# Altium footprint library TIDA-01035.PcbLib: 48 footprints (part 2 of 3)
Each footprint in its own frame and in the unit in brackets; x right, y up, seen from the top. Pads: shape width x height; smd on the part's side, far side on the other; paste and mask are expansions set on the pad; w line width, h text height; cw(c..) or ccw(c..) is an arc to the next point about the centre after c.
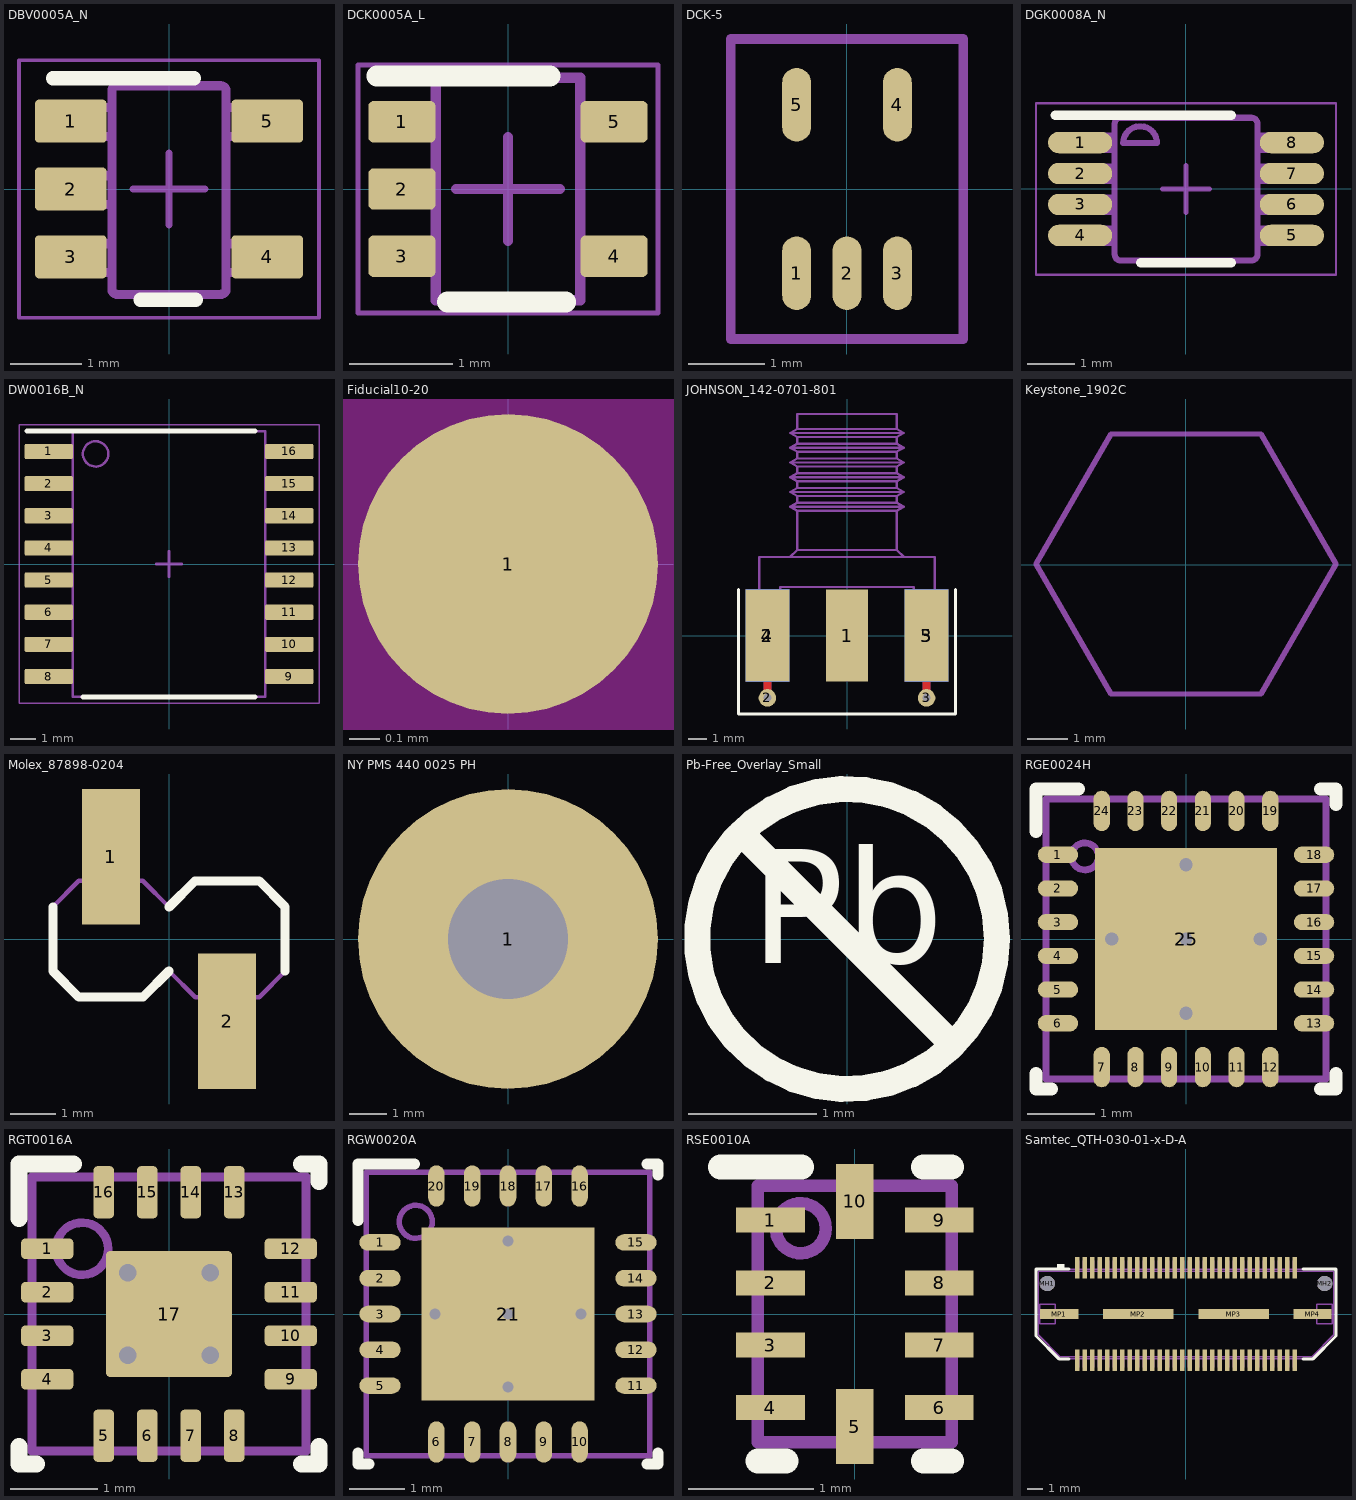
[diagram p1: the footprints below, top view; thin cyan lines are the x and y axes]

## DBV0005A_N [mm] "SOT23, 5-Leads, Body 2.9x1.6mm, Pitch 0.95mm, Lead Span 2.8mm, IPC Medium Density"
height 1.45
pads (5):
  rrect17% 1x0.6 smd: 1(-1.375,0.95) 2(-1.375,0) 3(-1.375,-0.95) 4(1.375,-0.95) 5(1.375,0.95)
Top Overlay:
  lines w0.2: -1.625,1.55 0.35,1.55 ; -0.4,-1.55 0.375,-1.55
Mechanical 5:
  lines w0.127: -0.801,1.371 cw(c-0.725,1.37) -0.725,1.446 ; -0.801,1.37 -0.801,-1.399 -0.801,-1.4 ccw(c-0.725,-1.399) -0.725,-1.475 ; -0.801,1.37 -0.801,1.371 ; -0.725,-1.475 -0.725,-1.475 ; -0.725,-1.475 0.723,-1.475 0.724,-1.475 ccw(c0.723,-1.399) 0.799,-1.4 0.799,-1.399 0.799,1.37 ; -0.725,1.446 0.723,1.446 0.724,1.446 cw(c0.723,1.37) 0.799,1.371 ; -0.725,1.446 -0.725,1.446 ; 0.799,1.37 0.799,1.371 ; -1.423,-1.167 -1.199,-1.167 -1.105,-1.167 -1.088,-1.167 -0.835,-1.167 -0.801,-1.167 -0.801,-0.767 -0.835,-0.767 -1.088,-0.767 -1.105,-0.767 -1.199,-0.767 -1.423,-0.767 -1.423,-1.167 ; -1.423,-0.215 -1.199,-0.215 -1.105,-0.215 -1.088,-0.215 -0.835,-0.215 -0.801,-0.215 -0.801,0.186 -0.835,0.186 -1.088,0.186 -1.105,0.186 -1.199,0.186 -1.423,0.186 -1.423,-0.215 ; -1.423,0.738 -1.199,0.738 -1.105,0.738 -1.088,0.738 -0.835,0.738 -0.801,0.738 -0.801,1.138 -0.835,1.138 -1.088,1.138 -1.105,1.138 -1.199,1.138 -1.423,1.138 -1.423,0.738 ; 0.799,-1.167 0.799,-0.767 0.834,-0.767 1.087,-0.767 1.103,-0.767 1.198,-0.767 1.422,-0.767 1.422,-1.167 1.198,-1.167 1.103,-1.167 1.087,-1.167 0.834,-1.167 0.799,-1.167 ; 0.799,0.738 0.799,1.138 0.834,1.138 1.087,1.138 1.103,1.138 1.198,1.138 1.422,1.138 1.422,0.738 1.198,0.738 1.103,0.738 1.087,0.738 0.834,0.738 0.799,0.738
  text ".Designator" at -0.25,0.95 h0.51
Mechanical 15:
  lines w0.05: -2.1,-1.8 2.1,-1.8 2.1,1.8 -2.1,1.8 -2.1,-1.8
  lines w0.1: -0.5,0 0.5,0 ; 0,-0.5 0,0.5
3D body: height 1.09, standoff 0, extent -1.422,-1.461 1.423,1.46

## DCK0005A_L [mm] "SOT353, 5-Leads, Body 2x1.3mm, Pitch 0.65mm, Lead Span 2.1mm, IPC High Density"
height 1.1
pads (5):
  rrect25% 0.65x0.4 smd: 1(-1.025,0.65) 2(-1.025,0) 3(-1.025,-0.65) 4(1.025,-0.65) 5(1.025,0.65)
Top Overlay:
  lines w0.2: -1.27,1.092 0.406,1.092 ; -0.584,-1.092 0.559,-1.092
Mechanical 5:
  lines w0.1: -0.7,-1.075 0.7,-1.075 0.7,1.075 -0.7,1.075 -0.7,-1.075
  lines w0.127: -0.865,0.762 -0.853,0.762 ; -0.711,-0.763 -0.853,-0.763 -0.865,-0.763 -0.959,-0.763 -1.143,-0.763 -1.143,-0.538 -0.959,-0.538 -0.865,-0.538 -0.853,-0.538 -0.711,-0.538 ; -0.711,-0.113 -0.853,-0.113 -0.865,-0.113 -0.959,-0.113 -1.143,-0.113 -1.143,0.112 -0.959,0.112 -0.865,0.112 -0.853,0.112 -0.711,0.112 ; -0.711,0.537 -0.853,0.537 -0.865,0.537 -0.959,0.537 -1.143,0.537 -1.143,0.762 -0.959,0.762 -0.711,0.762 ; 0.711,-0.763 0.847,-0.763 0.859,-0.763 0.953,-0.763 1.137,-0.763 1.137,-0.538 0.953,-0.538 0.859,-0.538 0.847,-0.538 0.711,-0.538 ; 0.711,0.537 0.847,0.537 0.859,0.537 0.953,0.537 1.137,0.537 1.137,0.762 0.953,0.762 0.859,0.762 0.847,0.762 0.711,0.762
  text ".Designator" at -0.254,0.914 h0.51
Mechanical 15:
  lines w0.05: -1.45,-1.2 -1.45,1.2 1.45,1.2 1.45,-1.2 -1.45,-1.2
  lines w0.1: -0.5,0 0.5,0 ; 0,-0.5 0,0.5
3D body: height 0.95, standoff 0, extent -1.14,-1 1.14,1

## DCK-5 [mil]
pads (5):
  oval 15x38 smd: 1(-25.9,-43.4) 2(0.1,-43.4) 3(26.1,-43.4) 4(26.1,43.6) 5(-25.9,43.6)
Mechanical 5:
  lines w5: -59.9,-77.4 60.1,-77.4 60.1,77.6 -59.9,77.6 -59.9,-77.4
  text "*" at -40,-55 h25
  text ".Designator" at -50,-15 h28

## DGK0008A_N [mm] "TSOP, 8-Leads, Body 3x3mm, Pitch 0.65mm, IPC Medium Density"
height 1.1
pads (8):
  oval 1.35x0.45 smd: 1(-2.225,0.975) 2(-2.225,0.325) 3(-2.225,-0.325) 4(-2.225,-0.975) 5(2.225,-0.975) 6(2.225,-0.325) 7(2.225,0.325) 8(2.225,0.975)
Top Overlay:
  lines w0.2: -2.75,1.55 0.95,1.55 ; -0.95,-1.55 0.95,-1.55
Mechanical 5:
  lines w0.127: -2.45,-1.131 -2.45,-0.826 -2.21,-0.826 -2.091,-0.826 -2.087,-0.826 -1.784,-0.826 -1.498,-0.826 -1.498,-1.131 -1.784,-1.131 -2.087,-1.131 -2.091,-1.131 -2.21,-1.131 -2.45,-1.131 ; -2.45,-0.48 -2.45,-0.175 -2.21,-0.175 -2.091,-0.175 -2.087,-0.175 -1.784,-0.175 -1.498,-0.175 -1.498,-0.48 -1.784,-0.48 -2.087,-0.48 -2.091,-0.48 -2.21,-0.48 -2.45,-0.48 ; -2.45,0.17 -2.45,0.475 -2.21,0.475 -2.091,0.475 -2.087,0.475 -1.784,0.475 -1.498,0.475 -1.498,0.17 -1.784,0.17 -2.087,0.17 -2.091,0.17 -2.21,0.17 -2.45,0.17 ; -2.45,0.82 -2.45,1.125 -2.21,1.125 -2.091,1.125 -2.087,1.125 -1.784,1.125 -1.498,1.125 -1.498,0.82 -1.784,0.82 -2.087,0.82 -2.091,0.82 -2.21,0.82 -2.45,0.82 ; -1.497,-1.377 ccw(c-1.37,-1.374) -1.373,-1.501 -1.371,-1.501 1.373,-1.501 1.375,-1.501 ccw(c1.373,-1.374) 1.5,-1.377 1.5,-1.374 1.5,1.369 1.5,1.372 ccw(c1.373,1.369) 1.375,1.496 1.373,1.496 -1.371,1.496 -1.373,1.496 ccw(c-1.37,1.369) -1.497,1.372 -1.498,1.369 -1.498,-1.374 -1.497,-1.377 ; -1.32,0.962 cw(c-0.964,0.962) -0.609,0.962 -1.32,0.962 ; 1.5,-1.131 1.786,-1.131 2.089,-1.131 2.093,-1.131 2.213,-1.131 2.452,-1.131 2.452,-0.826 2.213,-0.826 2.093,-0.826 2.089,-0.826 1.786,-0.826 1.5,-0.826 1.5,-1.131 ; 1.5,-0.48 1.786,-0.48 2.089,-0.48 2.093,-0.48 2.213,-0.48 2.452,-0.48 2.452,-0.175 2.213,-0.175 2.093,-0.175 2.089,-0.175 1.786,-0.175 1.5,-0.175 1.5,-0.48 ; 1.5,0.17 1.786,0.17 2.089,0.17 2.093,0.17 2.213,0.17 2.452,0.17 2.452,0.475 2.213,0.475 2.093,0.475 2.089,0.475 1.786,0.475 1.5,0.475 1.5,0.17 ; 1.5,0.82 1.786,0.82 2.089,0.82 2.093,0.82 2.213,0.82 2.452,0.82 2.452,1.125 2.213,1.125 2.093,1.125 2.089,1.125 1.786,1.125 1.5,1.125 1.5,0.82
  text ".Designator" at -1.15,-0.3 h0.64
Mechanical 15:
  lines w0.05: -3.15,-1.8 -3.15,1.8 3.15,1.8 3.15,-1.8 -3.15,-1.8
  lines w0.1: -0.5,0 0.5,0 ; 0,-0.5 0,0.5
3D body: height 0.96, standoff 0, extent -2.451,-1.499 2.451,1.499

## DW0016B_N [mm] "SOIC, 16-Leads, Body 10.5x7.6mm, Pitch 1.27mm, IPC Medium Density"
height 2.65
pads (16):
  rrect17% 1.9x0.6 smd: 1(-4.75,4.445) 2(-4.75,3.175) 3(-4.75,1.905) 4(-4.75,0.635) 5(-4.75,-0.635) 6(-4.75,-1.905) 7(-4.75,-3.175) 8(-4.75,-4.445) 9(4.75,-4.445) 10(4.75,-3.175) 11(4.75,-1.905) 12(4.75,-0.635) 13(4.75,0.635) 14(4.75,1.905) 15(4.75,3.175) 16(4.75,4.445)
Top Overlay:
  lines w0.2: -5.6,5.25 3.4,5.25 ; -3.4,-5.25 3.4,-5.25
Mechanical 5:
  circle w0.1: c-2.9,4.35 r0.5
  lines w0.1: -3.8,-5.25 -3.8,5.25 3.8,5.25 3.8,-5.25 -3.8,-5.25
  text ".Designator" at -2.179,-0.358 h1.02
Mechanical 15:
  lines w0.05: -5.925,-5.5 -5.925,5.5 5.925,5.5 5.925,-5.5 -5.925,-5.5
  lines w0.1: -0.5,0 0.5,0 ; 0,-0.5 0,0.5
3D body: height 2.59, standoff 0, extent -5.167,-5.15 5.167,5.15

## Fiducial10-20 [mm]
height 0.69
pads (1):
  round 1 smd mask+0.5: 1(0,0)
Top Layer keep-out:
  circle w1.178: c0,0 r0.5

## JOHNSON_142-0701-801 [mil] "Johnson Components recommended land pattern"
height 119
pads (7):
  rect 90x200 smd: 1(0,0)
  round 38 hole 18: 2(-172.5,-135) 3(172.5,-135)
  rect 95x200 smd: 2(-172.5,0) 3(172.5,0)
  rect 95x200 smd far side: 4(-172.5,0) 5(172.5,0)
Top Layer:
  lines w18: -172.5,-135 -172.5,0 ; 172.5,-135 172.5,0
Bottom Layer:
  lines w18: -172.5,-135 -172.5,0 ; 172.5,-135 172.5,0
Top Overlay:
  lines w7: -235,100 -235,-170 0,-170 235,-170 235,100
Mechanical 5:
  lines w5: -123.5,170.38 -108,185.38 ; 123.5,170.38 108,185.38 ; -123,279.27 -108,270.62 ; -123,279.27 -108,287.94 ; -123,279.27 123,279.27 ; -123,311.27 -108,319.94 ; -123,311.27 -108,302.62 ; -123,311.27 123,311.27 ; -123,343.27 -108,351.94 ; -123,343.27 -108,334.62 ; -123,343.27 123,343.27 ; -123,375.27 -108,383.94 ; -123,375.27 -108,366.62 ; -123,375.27 123,375.27 ; -123,407.27 -108,398.62 ; -123,407.27 -108,415.94 ; -123,407.27 123,407.27 ; -123,439.27 -108,430.62 ; -123,439.27 -108,447.94 ; -123,439.27 123,439.27 ; -108,185.38 -108,270.62 ; -108,185.38 108,185.38 ; -108,270.62 108,270.62 ; -108,287.94 -108,302.62 ; -108,287.94 108,287.94 ; -108,302.62 108,302.62 ; -108,319.94 -108,334.62 ; -108,319.94 108,319.94 ; -108,334.62 108,334.62 ; -108,351.94 -108,366.62 ; -108,351.94 108,351.94 ; -108,366.62 108,366.62 ; -108,383.94 -108,398.62 ; -108,383.94 108,383.94 ; -108,398.62 108,398.62 ; -108,415.94 -108,430.62 ; -108,415.94 108,415.94 ; -108,430.62 108,430.62 ; -108,447.94 -108,480.38 108,480.38 108,447.94 ; -108,447.94 108,447.94 ; 108,185.38 108,270.62 ; 108,270.62 123,279.27 ; 108,287.94 123,279.27 ; 108,287.94 108,302.62 ; 108,302.62 123,311.27 ; 108,319.94 108,334.62 ; 108,319.94 123,311.27 ; 108,334.62 123,343.27 ; 108,351.94 108,366.62 ; 108,351.94 123,343.27 ; 108,366.62 123,375.27 ; 108,383.94 108,398.62 ; 108,383.94 123,375.27 ; 108,398.62 123,407.27 ; 108,415.94 123,407.27 ; 108,415.94 108,430.62 ; 108,430.62 123,439.27 ; 108,447.94 123,439.27 ; -190,-91.62 -190,170.38 190,170.38 190,-91.62 145,-91.62 145,105.38 -145,105.38 -145,-91.62 -190,-91.62
  text ".Designator" at -66.5,-31 h60
3D body: height 164.6, standoff -152.4, extent -190,-92 190,480

## Keystone_1902C [mil] "Hex Standoff, 4-40 threaded, nylon"
height 500
pads (1):
  round 1 on Mech3: 0(0,0)
Mechanical 5:
  lines w5: -145.29,0.49 -72.56,126.47 72.92,126.47 145.65,0.49 72.92,-125.49 -72.56,-125.49 -145.29,0.49
  text ".Designator" at -60,-20 h40
3D body: height 501, standoff 1, extent -144.95,-125.98 146,125.98

## Molex_87898-0204 [mm] "Header, 2.54 mm, 2x1, R/A, SMT"
height 9.65
pads (2):
  rect 1.27x2.96 smd: 1(-1.27,1.8) 2(1.27,-1.8)
Top Overlay:
  lines w0.2: -2.54,0.7 -2.54,-0.7 -1.97,-1.27 -0.57,-1.27 0,-0.7 ; 0,0.7 0.57,1.27 1.97,1.27 2.54,0.7 2.54,-0.7
Mechanical 5:
  lines w0.1: -1.615,1.27 -1.615,2.4 -0.925,2.4 -0.925,1.27 ; 0.925,-1.27 0.925,-2.4 1.615,-2.4 1.615,-1.27 ; -2.54,-0.7 -2.54,0.7 -1.97,1.27 -0.57,1.27 0,0.7 0.57,1.27 1.97,1.27 2.54,0.7 2.54,-0.7 1.97,-1.27 0.57,-1.27 0,-0.7 -0.57,-1.27 -1.97,-1.27 -2.54,-0.7
  text ".Designator" at -1.524,-0.508 h1.02
3D body: height 0.69, standoff 0, extent 0.925,-2.4 1.615,0.345
3D body: height 3.81, standoff 1.32, extent 0,-1.27 2.54,1.27
3D body: height 3.81, standoff 1.32, extent -2.54,-1.27 0,1.27
3D body: height 0.69, standoff 0, extent -1.615,-0.345 -0.925,2.4
3D body: height 9.65, standoff 0, extent 0.926,-0.344 1.614,0.344
3D body: height 9.65, standoff 0, extent -1.614,-0.344 -0.926,0.344
3D body: height 3.81, standoff 1.32, extent 0,-0.7 0,-0.7
3D body: height 3.81, standoff 1.32, extent 0,-0.7 0,-0.7

## NY PMS 440 0025 PH [mm] "4-40 nylon screw and mounting hole"
height 1.905
pads (1):
  round 8 hole 3.2: 1(0,0)
Mechanical 5:
  circle w0.127: c0,0 r3.789
  text ".Designator" at -1.524,-0.508 h1.02
3D body: height 2.69, standoff -8.74, extent -3.302,-3.3 3.296,3.3

## Pb-Free_Overlay_Small [mm]
height 0.69
Top Overlay:
  circle w0.203: c0,0 r1.168
  lines w0.203: -0.826,0.826 0.826,-0.826
  text "Pb" at -0.752,-0.48 h1.52

## RGE0024H [mm] "QFN, 24-Leads, Body 4x4mm, Pitch 0.5mm, Thermal Pad 2.7x2.7mm, TI Recommended"
height 1
pads (25):
  oval 0.6x0.24 smd: 1(-1.9,1.25) 2(-1.9,0.75) 3(-1.9,0.25) 4(-1.9,-0.25) 5(-1.9,-0.75) 6(-1.9,-1.25) 13(1.9,-1.25) 14(1.9,-0.75) 15(1.9,-0.25) 16(1.9,0.25) 17(1.9,0.75) 18(1.9,1.25)
  oval 0.24x0.6 smd: 7(-1.25,-1.9) 8(-0.75,-1.9) 9(-0.25,-1.9) 10(0.25,-1.9) 11(0.75,-1.9) 12(1.25,-1.9) 19(1.25,1.9) 20(0.75,1.9) 21(0.25,1.9) 22(-0.25,1.9) 23(-0.75,1.9) 24(-1.25,1.9)
  rect 2.7x2.7 smd paste-1.35: 25(0,0)
via 0,1.1 diameter 0.5 hole 0.2
via -1.1,0 diameter 0.5 hole 0.2
via 0,0 diameter 0.5 hole 0.2
via 1.1,0 diameter 0.5 hole 0.2
via 0,-1.1 diameter 0.5 hole 0.2
Top Overlay:
  lines w0.2: -2.225,-2 -2.225,-2.225 -2,-2.225 ; -2.225,1.6 -2.225,2.225 -1.6,2.225 ; 2,-2.225 2.225,-2.225 2.225,-2 ; 2,2.225 2.225,2.225 2.225,2
Top Paste:
  rectangle: 0.1,0.1 1.288,1.288
  region: -0.1,1.288 -1.288,1.288 -1.288,0.1 -0.1,0.1
  region: -0.1,-0.1 -1.288,-0.1 -1.288,-1.288 -0.1,-1.288
  rectangle: 0.1,-1.288 1.288,-0.1
Mechanical 5:
  circle w0.1: c-1.5,1.225 r0.2
  lines w0.1: -2.075,-2.075 -2.075,2.075 2.075,2.075 2.075,-2.075 -2.075,-2.075
  text ".Designator" at -1.854,-0.508 h1.02
3D body: height 1, standoff 0, extent -2.075,-2.075 2.075,2.075
3D body: height 1.01, standoff 0.5, extent -1.703,1.022 -1.297,1.428

## RGT0016A [mm] "QFN, 16-Leads, Body 3x3mm, Pitch 0.5mm, Thermal Pad 1.45x1.45mm, TI Recommended"
height 1
pads (17):
  rrect42% 0.6x0.24 smd: 1(-1.4,0.75) 2(-1.4,0.25) 3(-1.4,-0.25) 4(-1.4,-0.75) 9(1.4,-0.75) 10(1.4,-0.25) 11(1.4,0.25) 12(1.4,0.75)
  rrect42% 0.24x0.6 smd: 5(-0.75,-1.4) 6(-0.25,-1.4) 7(0.25,-1.4) 8(0.75,-1.4) 13(0.75,1.4) 14(0.25,1.4) 15(-0.25,1.4) 16(-0.75,1.4)
  rrect7% 1.45x1.45 smd paste-0.725: 17(0,0)
via -0.475,0.475 diameter 0.5 hole 0.2
via -0.475,-0.475 diameter 0.5 hole 0.2
via 0.475,-0.475 diameter 0.5 hole 0.2
via 0.475,0.475 diameter 0.5 hole 0.2
Top Overlay:
  lines w0.2: -1.725,-1.525 -1.725,-1.725 -1.525,-1.725 ; -1.725,1.1 -1.725,1.725 -1.1,1.725 ; 1.525,-1.725 1.725,-1.725 1.725,-1.525 ; 1.525,1.725 1.725,1.725 1.725,1.525
Top Paste:
  rectangle: -0.668,-0.669 0.669,0.669
Mechanical 5:
  circle w0.1: c-1,0.75 r0.3
  lines w0.1: -1.575,-1.575 -1.575,1.575 1.575,1.575 1.575,-1.575 -1.575,-1.575
  text ".Designator" at -1.397,-1.016 h0.76
3D body: height 1, standoff 0, extent -1.575,-1.575 1.575,1.575
3D body: height 1.01, standoff 0.5, extent -1.305,0.445 -0.695,1.055

## RGW0020A [mm] "QFN, 20-Leads, Body 5x5mm, Pitch 0.65mm, Thermal Pad 3.15x3.15mm, TI Recommended"
height 1
pads (21):
  oval 0.75x0.3 smd: 1(-2.325,1.3) 2(-2.325,0.65) 3(-2.325,0) 4(-2.325,-0.65) 5(-2.325,-1.3) 11(2.325,-1.3) 12(2.325,-0.65) 13(2.325,0) 14(2.325,0.65) 15(2.325,1.3)
  oval 0.3x0.75 smd: 6(-1.3,-2.325) 7(-0.65,-2.325) 8(0,-2.325) 9(0.65,-2.325) 10(1.3,-2.325) 16(1.3,2.325) 17(0.65,2.325) 18(0,2.325) 19(-0.65,2.325) 20(-1.3,2.325)
  rect 3.15x3.15 smd paste-1.575: 21(0,0)
via 0,1.325 diameter 0.5 hole 0.2
via -1.325,0 diameter 0.5 hole 0.2
via 0,0 diameter 0.5 hole 0.2
via 1.325,0 diameter 0.5 hole 0.2
via 0,-1.325 diameter 0.5 hole 0.2
Top Overlay:
  lines w0.2: -2.725,-2.525 -2.725,-2.725 -2.525,-2.725 ; -2.725,1.7 -2.725,2.725 -1.7,2.725 ; 2.525,-2.725 2.725,-2.725 2.725,-2.525 ; 2.525,2.725 2.725,2.725 2.725,2.525
Top Paste:
  rectangle: 0.1,0.1 1.468,1.468
  region: -0.1,1.468 -1.468,1.468 -1.468,0.1 -0.1,0.1
  region: -0.1,-0.1 -1.468,-0.1 -1.468,-1.468 -0.1,-1.468
  rectangle: 0.1,-1.468 1.468,-0.1
Mechanical 5:
  circle w0.1: c-1.675,1.675 r0.3
  lines w0.1: -2.575,-2.575 -2.575,2.575 2.575,2.575 2.575,-2.575 -2.575,-2.575
  text ".Designator" at -1.854,-0.508 h1.02
3D body: height 1, standoff 0, extent -2.575,-2.575 2.575,2.575
3D body: height 1.01, standoff 0.5, extent -1.98,1.37 -1.37,1.98

## RSE0010A [mm] "QFN, 10-Leads, Body 1.5x2mm, Pitch 0.5mm, TI Recommended"
height 0.6
pads (10):
  rect 0.55x0.2 smd: 1(-0.675,0.75) 2(-0.675,0.25) 3(-0.675,-0.25) 4(-0.675,-0.75) 6(0.675,-0.75) 7(0.675,-0.25) 8(0.675,0.25) 9(0.675,0.75)
  rect 0.3x0.6 smd: 5(0,-0.9) 10(0,0.9)
Top Overlay:
  lines w0.2: -1.075,1.175 -0.425,1.175 ; -0.775,-1.175 -0.55,-1.175 ; 0.55,-1.175 0.775,-1.175 ; 0.55,1.175 0.775,1.175
Mechanical 5:
  circle w0.1: c-0.432,0.686 r0.2
  lines w0.1: -0.775,-1.025 0.775,-1.025 0.775,1.025 -0.775,1.025 -0.775,-1.025
  text ".Designator" at 0,0.675 h0.38
3D body: height 0.6, standoff 0, extent -0.775,-1.025 0.775,1.025
3D body: height 0.61, standoff 0.3, extent -0.635,0.482 -0.228,0.889

## Samtec_QTH-030-01-x-D-A [mil] "Header (Shrouded), 19.7mil, 30x2, SMT"
height 162
pads (66):
  rect 12x57 smd: 1(-285.7,121.5) 2(-285.7,-121.5) 3(-266,121.5) 4(-266,-121.5) 5(-246.3,121.5) 6(-246.3,-121.5) 7(-226.6,121.5) 8(-226.6,-121.5) 9(-206.9,121.5) 10(-206.9,-121.5) 11(-187.2,121.5) 12(-187.2,-121.5) 13(-167.5,121.5) 14(-167.5,-121.5) 15(-147.8,121.5) 16(-147.8,-121.5) 17(-128.1,121.5) 18(-128.1,-121.5) 19(-108.4,121.5) 20(-108.4,-121.5) 21(-88.7,121.5) 22(-88.7,-121.5) 23(-69,121.5) 24(-69,-121.5) 25(-49.3,121.5) 26(-49.3,-121.5) 27(-29.6,121.5) 28(-29.6,-121.5) 29(-9.9,121.5) 30(-9.9,-121.5) 31(9.8,121.5) 32(9.8,-121.5) 33(29.5,121.5) 34(29.5,-121.5) 35(49.2,121.5) 36(49.2,-121.5) 37(68.9,121.5) 38(68.9,-121.5) 39(88.6,121.5) 40(88.6,-121.5) 41(108.3,121.5) 42(108.3,-121.5) 43(128,121.5) 44(128,-121.5) 45(147.7,121.5) 46(147.7,-121.5) 47(167.4,121.5) 48(167.4,-121.5) 49(187.1,121.5) 50(187.1,-121.5) 51(206.8,121.5) 52(206.8,-121.5) 53(226.5,121.5) 54(226.5,-121.5) 55(246.2,121.5) 56(246.2,-121.5) 57(265.9,121.5) 58(265.9,-121.5) 59(285.6,121.5) 60(285.6,-121.5)
  round 40 hole 40 unplated mask+10: MH1(-364,80)
  round 40 hole 40 unplated: MH2(364,80)
  rect 100x25 smd: MP1(-332.7,0) MP4(332.3,0)
  rect 185x25 smd: MP2(-125.2,0) MP3(124.8,0)
Top Overlay:
  rectangle: -338.67,118.11 -318.9,131.28
  lines w7.87: -307,-117.5 -333.75,-117.5 -393.75,-57.5 -393.75,20 -393.75,117.5 -307,117.5 ; 307,-117.5 333.75,-117.5 393.75,-57.5 393.75,20 393.75,117.5 307,117.5
Mechanical 5:
  drawing of 212 lines, arcs and shapes, not listed
  text ".Designator" at -118.11,-11.33 h40
3D body: height 170.01, standoff -27, extent -393.75,-140 393.75,140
